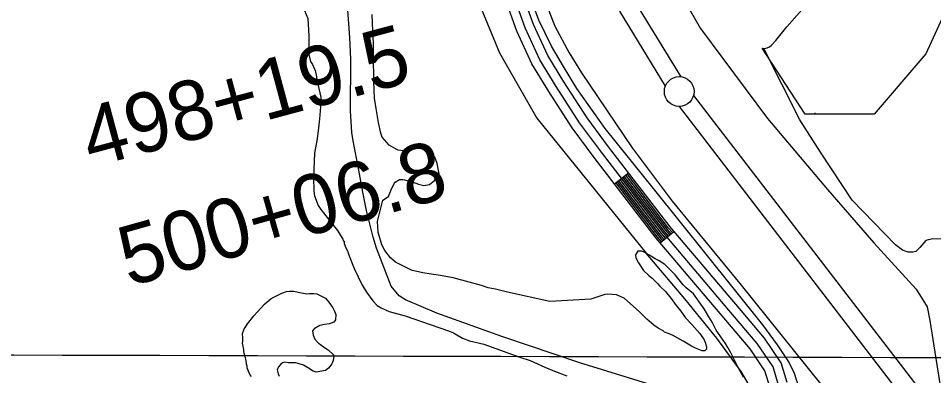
# Model space of a CAD drawing. Extents: x 3161615 to 3199515, y 867541 to 892976.
# Drawn here: x 3176709 to 3178243, y 879002 to 879602 of the extents above; entities that cross this region are included whole.
import ezdxf

# ---------------------------------------------------------------- set-up
doc = ezdxf.new("R2010")
doc.units = 0
for name, color, linetype in [('V-GRID-MAJR', 7, 'Continuous'), ('V-LEVE-TOET', 7, 'Continuous'), ('V-ROAD-CNTR', 7, 'Continuous'), ('V-SITE-VEGE', 7, 'Continuous'), ('V-SURV-IDEN', 7, 'Continuous'), ('V-SURV-LINE', 7, 'Continuous'), ('V-TOPO-SHOR', 7, 'Continuous'), ('V-WETL-SWMP', 7, 'Continuous')]:
    doc.layers.add(name, color=color, linetype=linetype)

msp = doc.modelspace()

# ---------------------------------------------------------------- linework, layer by layer
at = {"layer": 'V-GRID-MAJR'}
msp.add_spline([(3165838.644, 879070.158), (3171065.6580000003, 879053.813), (3176292.6750000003, 879038.2270000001), (3181519.694, 879023.402), (3186746.716, 879009.337), (3191973.739, 878996.033), (3197200.764, 878983.488), (3197200.765, 878983.488)], degree=3, dxfattribs=at)
at = {"layer": 'V-LEVE-TOET'}
for points in [[(3177190.069000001, 881032.5269999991), (3177212.360000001, 880895.6179999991), (3177219.356000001, 880848.2479999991), (3177238.408000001, 880756.812999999), (3177245.173000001, 880722.9289999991), (3177250.9280000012, 880702.3879999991), (3177266.206000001, 880652.7599999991), (3177303.383000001, 880541.258999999), (3177361.319000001, 880351.9829999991), (3177475.550000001, 880035.251999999), (3177559.455000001, 879716.182999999), (3177585.524000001, 879647.116999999), (3177608.242000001, 879589.290999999), (3177632.069000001, 879544.0099999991), (3177652.940000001, 879510.545999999), (3177737.862000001, 879384.5959999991), (3177804.654000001, 879295.1699999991), (3177918.604000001, 879156.7189999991), (3178101.6610000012, 878928.481999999)], [(3177799.617000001, 879676.6449999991), (3177852.302000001, 879584.9859999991), (3177964.547000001, 879433.7499999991), (3178065.335000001, 879314.5929999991), (3178143.219000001, 879225.2239999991), (3178214.229000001, 879147.3139999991), (3178232.554000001, 879117.525999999), (3178237.136000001, 879094.6109999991), (3178257.751000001, 878963.9979999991), (3178260.043000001, 878945.665999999), (3178276.076000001, 878931.915999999), (3178427.260000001, 878842.5499999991), (3178633.420000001, 878741.7239999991), (3178715.884000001, 878700.479999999), (3178725.047000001, 878700.479999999), (3178768.569000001, 878698.185999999), (3179196.925000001, 878711.935999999), (3179522.198000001, 878730.2699999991), (3179932.229000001, 878739.434999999), (3180383.489000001, 878760.057999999), (3180724.798000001, 878771.5149999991)]]:
    msp.add_lwpolyline(points, dxfattribs=at)
at = {"layer": 'V-ROAD-CNTR'}
for p, q in [((3177707.957547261, 879324.4703234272), (3177731.773499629, 879342.713286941)), ((3177784.848393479, 879224.9785224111), (3177807.718347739, 879244.3934835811))]:
    msp.add_line(p, q, dxfattribs=at)
for points in [[(3177983.375996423, 878986.1470000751), (3177974.0470150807, 879017.084938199), (3177947.552068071, 879056.244859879), (3177906.2771506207, 879105.118762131), (3177789.600383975, 879242.558487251), (3177686.347590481, 879377.3472176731), (3177649.7726636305, 879426.8651186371), (3177610.6307419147, 879487.459997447), (3177583.0647970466, 879532.7379068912), (3177558.2278467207, 879586.0538002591), (3177540.340882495, 879636.8266987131), (3177522.547918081, 879688.1435960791), (3177494.4579742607, 879769.334433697), (3177347.995267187, 880250.7674708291), (3177250.293462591, 880569.6438330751), (3177211.551540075, 880698.1205761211), (3177186.8395894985, 880780.0724122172)], [(3177997.737967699, 878990.473991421), (3177987.7489876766, 879023.599925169), (3177959.528044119, 879065.312841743), (3177917.725127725, 879114.8117427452), (3177801.2793606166, 879251.9794684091), (3177698.3355665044, 879386.3651996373), (3177662.117638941, 879435.3991015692), (3177623.338716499, 879495.4309815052), (3177596.3097705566, 879539.8268927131), (3177572.1328189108, 879591.726788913), (3177554.5008541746, 879641.7756888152), (3177536.721889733, 879693.0525862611), (3177508.7259457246, 879773.971424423), (3177362.341238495, 880255.147462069), (3177264.6454338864, 880574.0058243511), (3177225.918511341, 880702.432567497), (3177201.405560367, 880783.7234049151)], [(3177955.130052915, 878644.278683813), (3177980.2750026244, 878696.2175799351), (3177990.9229813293, 878727.9085165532), (3178000.040963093, 878775.1414220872), (3178003.7639556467, 878817.0283383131), (3177999.175964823, 878855.199261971), (3177993.4819762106, 878899.8451726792), (3177979.7580036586, 878946.1900799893), (3177969.0140251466, 878981.820008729), (3177960.345042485, 879010.5699512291), (3177935.576092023, 879047.176878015), (3177894.829173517, 879095.425781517), (3177777.921407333, 879233.137506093), (3177674.3596144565, 879368.3292357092), (3177637.4276883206, 879418.331135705), (3177597.922767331, 879479.4890133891), (3177569.819823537, 879525.6489210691), (3177544.3228745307, 879580.380811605), (3177526.180910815, 879631.8777086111), (3177508.3739464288, 879683.2346058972), (3177480.1900027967, 879764.697442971), (3177381.448200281, 880089.268793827)], [(3177791.709379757, 879230.8025107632), (3177784.928393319, 879238.790494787), (3177715.1035329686, 879329.9423124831)], [(3177793.9963751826, 879232.7445068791), (3177787.2643886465, 879240.674491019), (3177717.4845282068, 879331.7673088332)], [(3177796.283370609, 879234.6855029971), (3177789.600383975, 879242.558487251), (3177719.866523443, 879333.5913051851)], [(3177798.5703660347, 879236.626499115), (3177791.936379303, 879244.4424834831), (3177722.248518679, 879335.415301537)], [(3177800.8573614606, 879238.5684952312), (3177794.272374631, 879246.3264797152), (3177724.629513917, 879337.2402978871)], [(3177803.144356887, 879240.509491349), (3177796.6073699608, 879248.2104759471), (3177727.011509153, 879339.064294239)], [(3177805.4313523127, 879242.4514874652), (3177798.943365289, 879250.0944721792), (3177729.392504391, 879340.8882905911)], [(3177787.1353889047, 879226.9195185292), (3177780.257402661, 879235.0225023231), (3177710.340542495, 879326.2943197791)], [(3177789.422384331, 879228.8615146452), (3177782.593397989, 879236.9064985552), (3177712.7215377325, 879328.1183161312)]]:
    msp.add_lwpolyline(points, dxfattribs=at)
at = {"layer": 'V-SITE-VEGE'}
for p, q in [((3177188.375, 879615.4869999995), (3177194.026, 879601.6739999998)), ((3177302.8790000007, 879580.9889999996), (3177301.6630000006, 879608.5669999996)), ((3177194.026, 879601.6739999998), (3177195.574, 879573.0849999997)), ((3177302.5130000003, 879574.6009999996), (3177302.8790000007, 879580.9889999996)), ((3177303.5100000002, 879571.9079999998), (3177302.5130000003, 879574.6009999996)), ((3177195.865, 879563.3329999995), (3177195.486, 879554.2539999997)), ((3177195.574, 879573.0849999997), (3177195.8650000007, 879563.3329999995)), ((3177304.116, 879558.1189999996), (3177303.5100000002, 879571.9079999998)), ((3177195.486, 879554.2539999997), (3177194.44, 879545.8529999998)), ((3177194.44, 879545.8529999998), (3177198.734, 879529.6919999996)), ((3177304.366, 879539.6209999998), (3177304.116, 879558.1189999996)), ((3177198.734, 879529.6919999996), (3177202.073, 879524.6319999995)), ((3177304.499000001, 879496.2419999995), (3177304.3660000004, 879539.6209999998)), ((3177202.073, 879524.6319999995), (3177206.062, 879514.8629999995)), ((3177206.062, 879514.8629999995), (3177208.0470000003, 879507.4549999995)), ((3177208.0470000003, 879507.4549999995), (3177209.673, 879495.6789999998)), ((3177209.673, 879495.6789999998), (3177210.9980000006, 879491.6369999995)), ((3177210.998, 879491.6369999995), (3177215.94, 879469.7579999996)), ((3177305.716, 879468.3279999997), (3177304.499000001, 879496.2419999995)), ((3177215.94, 879469.7579999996), (3177215.1920000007, 879453.6199999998)), ((3177308.323, 879450.8299999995), (3177305.716, 879468.3279999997)), ((3177215.1920000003, 879453.6199999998), (3177213.416, 879433.4529999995)), ((3177312.249, 879427.2739999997), (3177308.323, 879450.8299999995)), ((3177213.416, 879433.4529999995), (3177211.6630000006, 879418.3299999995)), ((3177316.5350000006, 879409.4339999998), (3177312.249000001, 879427.2739999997)), ((3177211.6630000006, 879418.3299999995), (3177209.8960000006, 879399.8429999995)), ((3177318.856, 879402.6959999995), (3177316.535, 879409.4339999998)), ((3177209.896, 879399.8429999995), (3177205.077, 879375.6539999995)), ((3177330.228, 879389.1939999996), (3177318.856, 879402.6959999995)), ((3177205.077, 879375.6539999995), (3177203.539, 879334.9769999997)), ((3177341.965, 879382.4129999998), (3177330.228, 879389.1939999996)), ((3177345.6580000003, 879381.0509999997), (3177341.965, 879382.4129999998)), ((3177354.732, 879379.6619999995), (3177345.6580000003, 879381.0509999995)), ((3177361.464, 879381.6489999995), (3177354.732, 879379.6619999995)), ((3177378.293, 879384.9339999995), (3177361.464, 879381.6489999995)), ((3177396.7680000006, 879380.8109999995), (3177378.293, 879384.9339999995)), ((3177401.4540000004, 879376.0819999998), (3177396.7680000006, 879380.8109999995)), ((3177406.803, 879369.3319999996), (3177401.454, 879376.0819999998)), ((3177410.784, 879358.2179999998), (3177406.803, 879369.3319999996)), ((3177414.403, 879341.0509999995), (3177410.784, 879358.2179999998)), ((3177203.539, 879334.9769999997), (3177204.106, 879312.4429999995)), ((3177340.7, 879327.2719999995), (3177347.7800000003, 879331.6119999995)), ((3177347.7800000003, 879331.6119999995), (3177353.498, 879331.5829999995)), ((3177353.498, 879331.5829999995), (3177355.8470000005, 879330.8989999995)), ((3177355.8470000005, 879330.8989999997), (3177368.9480000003, 879327.8129999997)), ((3177398.181, 879323.3049999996), (3177406.617, 879329.6539999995)), ((3177406.617, 879329.6539999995), (3177414.403, 879341.0509999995)), ((3177332.555, 879311.5049999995), (3177334.934, 879316.8719999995)), ((3177334.934, 879316.8719999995), (3177339.3460000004, 879325.5969999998)), ((3177339.346, 879325.5969999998), (3177340.7, 879327.2719999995)), ((3177368.9480000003, 879327.8129999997), (3177379.687, 879323.7269999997)), ((3177379.687, 879323.7269999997), (3177388.42, 879321.6689999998)), ((3177388.42, 879321.6689999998), (3177398.181, 879323.3049999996)), ((3177204.106, 879312.4429999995), (3177205.079, 879304.3669999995)), ((3177205.079, 879304.3669999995), (3177211.3910000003, 879287.8629999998)), ((3177319.7080000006, 879296.7709999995), (3177329.151, 879302.7779999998)), ((3177329.151, 879302.7779999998), (3177332.555, 879311.5049999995)), ((3177211.3910000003, 879287.8629999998), (3177215.7310000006, 879281.1159999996)), ((3177310.7970000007, 879260.8329999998), (3177319.7080000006, 879296.7709999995)), ((3177215.731, 879281.1159999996), (3177243.475, 879245.6799999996)), ((3177312.056, 879243.0049999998), (3177310.7970000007, 879260.8329999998)), ((3177243.475, 879245.6799999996), (3177252.822, 879231.1759999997)), ((3177318.014, 879222.1299999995), (3177312.056, 879243.0049999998)), ((3177252.822, 879231.1759999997), (3177253.486, 879229.1569999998)), ((3177253.486, 879229.1569999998), (3177254.819, 879226.7949999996)), ((3177254.819, 879226.7949999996), (3177255.142, 879224.1039999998)), ((3177255.1420000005, 879224.1039999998), (3177257.8010000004, 879217.0299999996)), ((3177323.011, 879212.3549999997), (3177318.0140000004, 879222.1299999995)), ((3177257.8010000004, 879217.0299999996), (3177260.7950000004, 879210.6259999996)), ((3177260.795, 879210.6259999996), (3177261.4560000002, 879207.9329999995)), ((3177261.4560000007, 879207.9329999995), (3177268.1, 879190.7549999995)), ((3177332.37, 879200.2039999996), (3177323.011, 879212.3549999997)), ((3177747.369, 879211.3799999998), (3177743.3040000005, 879205.0089999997)), ((3177754.092, 879211.3469999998), (3177747.369, 879211.3799999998)), ((3177757.7830000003, 879209.6489999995), (3177754.092, 879211.3469999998)), ((3177765.8320000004, 879204.9039999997), (3177757.7830000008, 879209.6489999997)), ((3177268.1, 879190.7549999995), (3177272.427, 879180.9799999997)), ((3177341.078, 879192.7659999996), (3177332.37, 879200.2039999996)), ((3177368.9230000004, 879178.8499999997), (3177341.078, 879192.7659999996)), ((3177743.3040000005, 879205.0089999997), (3177743.955, 879200.2979999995)), ((3177743.955, 879200.2979999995), (3177748.286, 879191.8709999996)), ((3177748.286, 879191.8709999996), (3177756.632, 879178.7189999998)), ((3177776.225, 879198.4649999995), (3177765.832, 879204.9039999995)), ((3177782.934, 879195.0719999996), (3177776.225, 879198.4649999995)), ((3177792.656, 879188.6389999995), (3177782.934, 879195.0719999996)), ((3177272.427, 879180.9799999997), (3177284.748, 879155.3689999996)), ((3177374.6350000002, 879177.8129999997), (3177368.9230000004, 879178.8499999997)), ((3177386.7260000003, 879175.0689999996), (3177374.6350000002, 879177.8129999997)), ((3177756.632, 879178.7189999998), (3177765.6720000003, 879170.6059999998)), ((3177809.7260000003, 879171.4069999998), (3177792.656, 879188.6389999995)), ((3177404.872, 879171.9559999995), (3177386.7260000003, 879175.0689999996)), ((3177416.6310000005, 879170.2189999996), (3177404.872, 879171.9559999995)), ((3177437.7970000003, 879166.4219999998), (3177416.6310000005, 879170.2189999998)), ((3177485.151, 879153.7599999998), (3177437.7970000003, 879166.4219999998)), ((3177765.6720000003, 879170.6059999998), (3177771.365, 879165.8709999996)), ((3177771.365, 879165.8709999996), (3177780.401, 879156.7499999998)), ((3177823.434, 879154.5319999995), (3177809.7260000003, 879171.4069999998)), ((3177284.748, 879155.3689999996), (3177292.42, 879142.2189999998)), ((3177496.231, 879149.6719999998), (3177485.151, 879153.7599999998)), ((3177508.66, 879147.2589999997), (3177496.231, 879149.6719999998)), ((3177528.8120000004, 879142.4589999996), (3177508.66, 879147.2589999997)), ((3177780.401, 879156.7499999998), (3177784.0810000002, 879152.6989999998)), ((3177784.0810000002, 879152.6989999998), (3177793.453, 879143.2389999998)), ((3177828.453, 879149.4649999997), (3177823.4340000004, 879154.5319999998)), ((3177840.514, 879139.6569999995), (3177828.453, 879149.4649999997)), ((3177292.4200000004, 879142.2189999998), (3177303.113, 879127.7089999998)), ((3177600.026, 879126.6579999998), (3177528.8120000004, 879142.4589999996)), ((3177668.642, 879130.7069999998), (3177600.026, 879126.6579999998)), ((3177675.04, 879132.6959999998), (3177668.642, 879130.7069999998)), ((3177691.8800000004, 879138.3339999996), (3177675.04, 879132.6959999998)), ((3177696.927, 879138.9809999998), (3177691.8800000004, 879138.3339999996)), ((3177711.381, 879137.9059999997), (3177696.927, 879138.9809999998)), ((3177724.132, 879132.1309999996), (3177711.381, 879137.9059999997)), ((3177750.252, 879109.1419999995), (3177724.132, 879132.1309999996)), ((3177793.453, 879143.2389999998), (3177804.821, 879129.3989999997)), ((3177804.821, 879129.3989999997), (3177810.1670000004, 879121.9769999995)), ((3177855.882, 879118.4009999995), (3177840.514, 879139.6569999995)), ((3177303.113, 879127.7089999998), (3177310.475, 879119.9409999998)), ((3177310.475, 879119.9409999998), (3177316.844, 879115.8759999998)), ((3177316.844, 879115.8759999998), (3177330.603, 879109.7579999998)), ((3177810.167, 879121.9769999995), (3177819.1920000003, 879110.5019999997)), ((3177858.553, 879114.3519999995), (3177855.882, 879118.4009999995)), ((3177866.562, 879101.2019999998), (3177858.553000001, 879114.3519999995)), ((3177330.603, 879109.7579999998), (3177357.471, 879102.5719999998)), ((3177357.471, 879102.5719999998), (3177384.6640000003, 879093.3659999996)), ((3177762.303, 879097.3169999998), (3177750.252, 879109.1419999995)), ((3177819.1920000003, 879110.5019999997), (3177824.5380000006, 879103.0799999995)), ((3177824.5380000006, 879103.0799999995), (3177827.2060000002, 879099.0309999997)), ((3177827.2060000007, 879099.0309999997), (3177837.9190000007, 879088.2209999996)), ((3177871.9, 879092.0959999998), (3177866.562, 879101.2019999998)), ((3177384.6640000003, 879093.3659999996), (3177429.986, 879077.6869999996)), ((3177774.359, 879086.8349999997), (3177762.303, 879097.3169999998)), ((3177781.396, 879081.7599999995), (3177774.359, 879086.8349999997)), ((3177837.919, 879088.2209999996), (3177851.299, 879073.0249999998)), ((3177878.5620000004, 879078.6139999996), (3177871.9, 879092.0959999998)), ((3177429.986, 879077.6869999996), (3177438.379, 879074.2849999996)), ((3177438.379, 879074.2849999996), (3177441.058, 879072.2529999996)), ((3177441.058, 879072.2529999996), (3177453.465, 879065.1339999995)), ((3177789.785, 879077.3489999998), (3177781.396, 879081.7599999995)), ((3177792.128, 879075.3189999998), (3177789.785, 879077.3489999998)), ((3177798.17, 879073.2749999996), (3177792.128, 879075.3189999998)), ((3177805.217, 879070.2149999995), (3177798.17, 879073.2749999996)), ((3177823.327, 879060.0429999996), (3177805.217, 879070.2149999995)), ((3177851.2990000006, 879073.0249999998), (3177858.6470000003, 879062.5679999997)), ((3177894.2600000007, 879056.0129999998), (3177878.5620000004, 879078.6139999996)), ((3177453.465, 879065.1339999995), (3177464.8780000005, 879060.7109999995)), ((3177464.8780000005, 879060.7109999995), (3177489.061, 879054.8799999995)), ((3177489.061, 879054.8799999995), (3177549.487, 879033.4149999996)), ((3177837.411, 879051.5699999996), (3177823.327, 879060.0429999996)), ((3177858.6470000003, 879062.5679999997), (3177860.9710000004, 879056.5039999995)), ((3177860.971, 879056.5039999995), (3177862.2840000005, 879049.4359999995)), ((3177898.2660000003, 879049.6039999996), (3177894.2600000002, 879056.0129999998)), ((3177844.1210000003, 879048.1769999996), (3177837.411, 879051.5699999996)), ((3177852.1750000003, 879044.7749999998), (3177844.1210000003, 879048.1769999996)), ((3177855.198, 879044.0889999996), (3177852.1750000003, 879044.7749999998)), ((3177859.569, 879044.0689999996), (3177855.198, 879044.0889999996)), ((3177862.2720000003, 879046.7469999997), (3177859.569, 879044.0689999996)), ((3177862.2840000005, 879049.4359999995), (3177862.2720000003, 879046.7469999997)), ((3177902.599, 879041.8509999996), (3177898.2660000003, 879049.6039999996)), ((3177906.597, 879033.7609999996), (3177902.599, 879041.8509999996)), ((3177549.487, 879033.4149999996), (3177566.946, 879027.6129999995)), ((3177566.946, 879027.6129999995), (3177579.361, 879022.1779999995)), ((3177579.361, 879022.1779999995), (3177591.1040000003, 879016.4059999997)), ((3177911.5960000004, 879023.9879999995), (3177906.5970000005, 879033.7609999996)), ((3177915.594, 879015.8979999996), (3177911.596, 879023.9879999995)), ((3177591.1040000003, 879016.4059999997), (3177607.552, 879009.9409999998)), ((3177607.552, 879009.9409999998), (3177628.362, 879002.1089999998)), ((3177921.2600000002, 879005.7829999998), (3177915.5940000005, 879015.8979999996)), ((3177924.259, 878999.3789999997), (3177921.2600000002, 879005.7829999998))]:
    msp.add_line(p, q, dxfattribs=at)
for points in [[(3178256.799000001, 879231.2599999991), (3178241.883000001, 879231.8459999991), (3178230.414000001, 879228.908999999), (3178220.246000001, 879217.587999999), (3178213.610000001, 879210.550999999), (3178208.437000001, 879209.354999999), (3178200.352000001, 879209.724999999), (3178191.046000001, 879212.8999999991), (3178179.296000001, 879222.096999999), (3178106.924000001, 879296.6939999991), (3178053.877000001, 879377.621999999), (3178018.788000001, 879431.7139999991), (3177958.407000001, 879551.7899999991), (3177961.817000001, 879552.052999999), (3177964.416000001, 879552.7279999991), (3177968.205000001, 879554.491999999), (3177971.656000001, 879557.133999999), (3177978.949000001, 879564.8439999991), (3177997.278000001, 879588.047999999), (3178030.941000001, 879626.140999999)], [(3177086.502000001, 879046.091999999), (3177084.8570000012, 879053.8339999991), (3177084.5360000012, 879056.8629999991), (3177084.886000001, 879059.5489999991), (3177084.898000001, 879062.9119999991), (3177085.248000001, 879065.6009999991), (3177085.259000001, 879067.9539999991), (3177084.261000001, 879070.3139999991), (3177084.274000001, 879073.0049999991), (3177087.337000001, 879080.7259999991), (3177089.367000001, 879083.4049999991), (3177093.092000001, 879089.101999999), (3177103.244000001, 879102.841999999), (3177109.329000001, 879109.5389999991), (3177121.494000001, 879122.258999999), (3177125.207000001, 879125.6059999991), (3177132.633000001, 879131.6229999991), (3177138.027000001, 879134.6229999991), (3177150.498000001, 879140.6179999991), (3177158.241000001, 879143.2719999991), (3177163.292000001, 879144.258999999), (3177170.353000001, 879144.2239999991), (3177177.742000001, 879142.5099999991), (3177192.527000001, 879139.748999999), (3177196.561000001, 879140.0689999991), (3177201.606000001, 879140.0419999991), (3177204.299000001, 879140.3679999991), (3177209.339000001, 879139.670999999), (3177223.763000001, 879132.2059999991), (3177229.448000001, 879125.4539999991), (3177235.793000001, 879116.008999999), (3177238.793000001, 879110.613999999), (3177241.122000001, 879104.885999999), (3177240.407000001, 879096.1469999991), (3177237.362000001, 879091.790999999), (3177230.288000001, 879089.4709999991), (3177221.877000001, 879088.1639999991), (3177214.133000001, 879086.5199999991), (3177204.356000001, 879080.8489999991), (3177201.986000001, 879077.4959999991), (3177202.304000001, 879073.459999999), (3177202.961000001, 879070.430999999), (3177205.958000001, 879063.356999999), (3177211.979000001, 879056.937999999), (3177215.329000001, 879054.5689999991), (3177220.0190000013, 879050.8479999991), (3177228.066000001, 879045.430999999), (3177236.770000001, 879037.319999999), (3177237.431000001, 879034.962999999), (3177236.389000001, 879027.569999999), (3177234.007000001, 879021.863999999), (3177228.594000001, 879014.8269999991), (3177223.867000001, 879010.814999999), (3177207.717000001, 879008.199999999), (3177202.679000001, 879009.905999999), (3177195.304000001, 879014.6469999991), (3177186.921000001, 879019.729999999), (3177177.8570000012, 879022.797999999), (3177173.489000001, 879023.491999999), (3177161.385000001, 879023.885999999), (3177155.335000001, 879024.5859999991), (3177151.296000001, 879023.596999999), (3177148.595000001, 879021.591999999), (3177144.878000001, 879017.2379999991), (3177142.496000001, 879011.8699999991), (3177143.485000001, 879007.4909999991), (3177144.149000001, 879005.471999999), (3177146.148000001, 879001.4269999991)], [(3177089.463000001, 879031.9569999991), (3177087.145000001, 879039.699999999), (3177086.485000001, 879042.3929999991), (3177086.502000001, 879046.091999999)], [(3177099.740000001, 879000.6349999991), (3177096.7320000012, 879004.3479999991), (3177092.412000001, 879015.4639999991), (3177092.089000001, 879018.1569999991), (3177091.095000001, 879021.523999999), (3177090.450000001, 879027.579999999), (3177089.463000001, 879031.9569999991)]]:
    msp.add_lwpolyline(points, dxfattribs=at)
at = {"layer": 'V-SURV-LINE'}
for points in [[(3177742.5129330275, 879630.0183714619), (3177819.1679034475, 879504.1549394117)], [(3177793.554030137, 879488.5366890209), (3177716.8994021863, 879614.3995587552)], [(3177840.8242336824, 879472.5626374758), (3178242.972897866, 878948.8153300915)], [(3178219.177843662, 878930.5452617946), (3177817.0288712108, 879454.2929706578)]]:
    msp.add_lwpolyline(points, dxfattribs=at)
msp.add_circle((3177816.75424, 879479.2809800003), 25, dxfattribs=at)
at = {"layer": 'V-TOPO-SHOR'}
for points in [[(3177278.7859239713, 880092.7023307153), (3177345.6505136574, 880064.3310299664), (3177459.1350611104, 879694.0693030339), (3177481.846575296, 879625.301890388), (3177515.0938773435, 879544.1737586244), (3177578.211239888, 879434.7765589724), (3177761.543000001, 879207.969999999)], [(3178047.727000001, 878781.1479999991), (3178049.142000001, 878827.5229999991), (3178047.620000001, 878865.7549999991), (3178044.143000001, 878888.1909999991), (3178034.967000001, 878925.6229999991), (3178025.031000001, 878958.439999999), (3178009.931000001, 879006.067999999), (3178000.731000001, 879025.5469999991), (3177981.326000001, 879054.2059999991), (3177956.996000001, 879087.5439999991), (3177907.223000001, 879149.783999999), (3177773.493000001, 879316.2479999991), (3177692.343000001, 879417.4169999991), (3177645.114000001, 879484.6079999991), (3177622.603000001, 879521.2999999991), (3177602.729000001, 879555.6529999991), (3177581.534000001, 879598.9069999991), (3177563.770000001, 879646.743999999), (3177536.406000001, 879725.9729999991), (3177498.959000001, 879856.327999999), (3177474.919000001, 879930.721999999), (3177447.294000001, 880018.1279999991)], [(3177792.898000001, 878979.5419999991), (3177650.324000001, 879023.7239999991), (3177519.285000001, 879067.9069999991), (3177410.201000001, 879106.935999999), (3177357.546000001, 879129.2799999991), (3177347.284000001, 879136.2899999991), (3177333.544000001, 879152.491999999), (3177309.072000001, 879216.1519999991), (3177303.584000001, 879234.9119999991), (3177292.5530000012, 879279.5889999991), (3177286.407000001, 879310.5539999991), (3177279.399000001, 879347.3649999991), (3177270.275000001, 879396.2649999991), (3177267.918000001, 879410.613999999), (3177265.278000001, 879446.8429999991), (3177265.995000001, 879533.4219999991), (3177264.291000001, 879570.170999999), (3177260.518000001, 879623.5199999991)], [(3177969.872000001, 878910.0169999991), (3177965.587000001, 878924.8339999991), (3177959.654000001, 878939.5939999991), (3177952.130000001, 878954.398999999), (3177945.4990000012, 878965.8759999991), (3177920.798000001, 879009.385999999), (3177879.797000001, 879065.410999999), (3177826.311000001, 879131.2559999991), (3177761.543000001, 879207.969999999)]]:
    msp.add_lwpolyline(points, dxfattribs=at)
at = {"layer": 'V-WETL-SWMP'}
msp.add_line((3178044.833160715, 879441.1715906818), (3178044.839228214, 879443.3672788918), dxfattribs=at)
msp.add_lwpolyline([(3178302.707000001, 879701.836999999), (3178230.355000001, 879542.5419999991), (3178143.531000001, 879441.1719999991), (3178027.767000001, 879441.1719999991), (3177955.910000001, 879552.2309999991), (3177958.408000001, 879551.790999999), (3177961.819000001, 879552.052999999), (3177964.416000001, 879552.7279999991), (3177968.205000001, 879554.491999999), (3177971.655000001, 879557.133999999), (3177978.948000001, 879564.844999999), (3177997.278000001, 879588.0489999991), (3178030.943000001, 879626.1419999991), (3178047.664000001, 879645.437999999), (3178055.779000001, 879655.4269999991), (3178063.648000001, 879665.7479999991), (3178065.291000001, 879668.6519999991), (3178066.1780000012, 879671.388999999), (3178066.8570000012, 879676.4949999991), (3178066.985000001, 879684.501999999)], dxfattribs=at)

# ---------------------------------------------------------------- texts
at = {"layer": 'V-SURV-IDEN'}
for s, height, rotation, p in [('498+19.5', 100.00000000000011, 15.066199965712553, (3176830.4326145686, 879351.3486546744)), ('500+06.8', 100, 15.734354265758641, (3176893.710108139, 879151.2681301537))]:
    msp.add_text(s, height=height, rotation=rotation, dxfattribs=at).set_placement(p)

doc.saveas('drawing.dxf')
